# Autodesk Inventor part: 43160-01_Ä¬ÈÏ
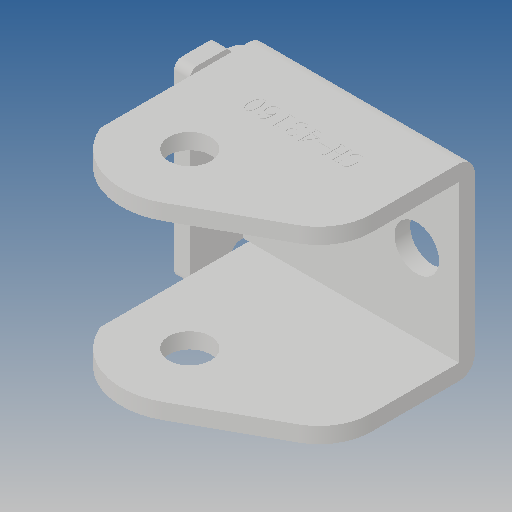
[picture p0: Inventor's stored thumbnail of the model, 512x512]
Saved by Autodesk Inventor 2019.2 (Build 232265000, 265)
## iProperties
Created: 2010-06
Part Number: 43160-01_Ä¬ÈÏ
Material: Ogólny
Document SubType Name: Modeling
Designer: CADENGINEERING4
Density: 1 g/cm^3
Appearance: Domyślna
Author: CADENGINEERING4
Revision Number: ÈÎºÎ
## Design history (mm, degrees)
feature "NONE"
node "Bryła1"
